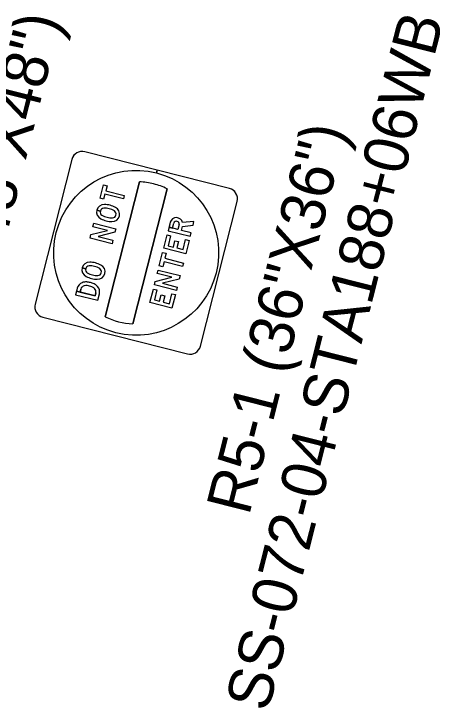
# Model space of a CAD drawing. Extents: x 670257 to 671518, y 737783 to 738188.
# Drawn here: x 670291.975 to 670294.377, y 738129.693 to 738133.598 of the extents above; entities that cross this region are included whole.
import ezdxf

# ---------------------------------------------------------------- set-up
doc = ezdxf.new("R2010")
doc.units = 0
doc.layers.add('Default', color=7, linetype='Continuous')
doc.layers.add('R_SIGN_HWY72', color=7, linetype='Continuous')

msp = doc.modelspace()

# ---------------------------------------------------------------- linework, layer by layer
at = {"layer": 'R_SIGN_HWY72'}
for p, q in [((670293.1871, 738132.6159), (670292.3734, 738132.8223)), ((670293.1871, 738132.6159), (670292.3735, 738132.8222)), ((670292.7803, 738132.7191), (670292.3735, 738132.8222)), ((670292.7803, 738132.7191), (670292.3735, 738132.8222)), ((670292.3006, 738132.7789), (670292.0941, 738131.9649)), ((670292.3006, 738132.7788), (670292.0942, 738131.9649)), ((670292.3006, 738132.7788), (670292.0942, 738131.9649)), ((670292.3006, 738132.7788), (670292.0942, 738131.9649)), ((670292.7803, 738132.7191), (670292.7764, 738132.7036)), ((670293.1871, 738132.6159), (670292.7803, 738132.7191)), ((670293.1871, 738132.6159), (670292.7803, 738132.7191)), ((670292.6812, 738132.6534), (670292.4885, 738131.8939)), ((670292.6435, 738131.8546), (670292.8361, 738132.6141)), ((670293.0241, 738131.7291), (670293.2305, 738132.543)), ((670293.0241, 738131.7291), (670293.2305, 738132.543)), ((670293.0241, 738131.7291), (670293.2305, 738132.543)), ((670293.0241, 738131.7291), (670293.2305, 738132.543)), ((670292.4611, 738132.4887), (670292.4411, 738132.4937)), ((670292.4411, 738132.4937), (670292.4611, 738132.4887)), ((670292.4611, 738132.4887), (670292.4411, 738132.4937)), ((670292.4411, 738132.4937), (670292.4611, 738132.4887)), ((670292.4611, 738132.4887), (670292.4611, 738132.4887)), ((670292.4611, 738132.4887), (670292.4611, 738132.4887)), ((670292.9043, 738132.4133), (670292.8972, 738132.3851)), ((670292.3788, 738132.1642), (670292.3588, 738132.1693)), ((670292.3588, 738132.1693), (670292.3788, 738132.1642)), ((670292.3788, 738132.1642), (670292.3588, 738132.1693)), ((670292.3588, 738132.1693), (670292.3788, 738132.1642)), ((670292.3788, 738132.1642), (670292.3788, 738132.1642)), ((670292.3788, 738132.1642), (670292.3788, 738132.1642)), ((670292.3513, 738132.0499), (670292.347, 738132.0332)), ((670292.4356, 738132.0285), (670292.4313, 738132.0118)), ((670292.4356, 738132.0285), (670292.4313, 738132.0118)), ((670292.4462, 738131.987), (670292.4554, 738132.0235)), ((670292.1375, 738131.8921), (670292.9512, 738131.6857)), ((670292.1375, 738131.8921), (670292.9512, 738131.6857)), ((670292.1375, 738131.892), (670292.9512, 738131.6857)), ((670292.1375, 738131.892), (670292.9512, 738131.6857)), ((670292.1375, 738131.892), (670292.9512, 738131.6857))]:
    msp.add_line(p, q, dxfattribs=at)
for points in [[(670292.7803, 738132.7191), (670292.7764, 738132.7036)], [(670292.7764, 738132.7036), (670292.7803, 738132.7191)], [(670292.7764, 738132.7036), (670292.7803, 738132.7191)], [(670292.4885, 738131.8939), (670292.4885, 738131.8939), (670292.6812, 738132.6534), (670292.6812, 738132.6534)], [(670292.8361, 738132.6141), (670292.8361, 738132.6141), (670292.6435, 738131.8546), (670292.6435, 738131.8546)], [(670292.8544, 738132.4259), (670292.8423, 738132.3782), (670292.9663, 738132.3468), (670292.9712, 738132.3663), (670292.917, 738132.38), (670292.9228, 738132.4028)], [(670292.8544, 738132.4259), (670292.8472, 738132.3978), (670292.8671, 738132.3927), (670292.8742, 738132.4209)], [(670292.8544, 738132.4259), (670292.8472, 738132.3978), (670292.8671, 738132.3927), (670292.8742, 738132.4209)], [(670292.9663, 738132.3468), (670292.9712, 738132.3663), (670292.917, 738132.38), (670292.9228, 738132.4028), (670292.9822, 738132.4095), (670292.9875, 738132.4304), (670292.9235, 738132.424)], [(670292.9663, 738132.3468), (670292.9712, 738132.3663), (670292.917, 738132.38), (670292.9228, 738132.4028), (670292.9822, 738132.4095), (670292.9875, 738132.4304), (670292.9235, 738132.424)], [(670292.9228, 738132.4028), (670292.9822, 738132.4095), (670292.9875, 738132.4304), (670292.9235, 738132.424)], [(670292.9043, 738132.4133), (670292.8972, 738132.3851), (670292.8472, 738132.3977), (670292.8423, 738132.3782), (670292.9663, 738132.3468)], [(670292.9043, 738132.4133), (670292.8972, 738132.3851), (670292.8472, 738132.3977), (670292.8423, 738132.3782), (670292.9663, 738132.3468)], [(670292.8972, 738132.3851), (670292.8671, 738132.3927), (670292.8742, 738132.4209)], [(670292.3314, 738132.0549), (670292.3222, 738132.0185), (670292.4462, 738131.987)], [(670292.4313, 738132.0118), (670292.3272, 738132.0382), (670292.3222, 738132.0185), (670292.4462, 738131.987), (670292.4554, 738132.0235)], [(670292.4313, 738132.0118), (670292.3272, 738132.0382), (670292.3222, 738132.0185), (670292.4462, 738131.987), (670292.4554, 738132.0235)], [(670292.3314, 738132.0549), (670292.3272, 738132.0382), (670292.347, 738132.0332), (670292.3513, 738132.0499)], [(670292.3314, 738132.0549), (670292.3272, 738132.0382), (670292.347, 738132.0332), (670292.3513, 738132.0499)], [(670292.347, 738132.0332), (670292.4313, 738132.0118), (670292.4356, 738132.0285)]]:
    msp.add_lwpolyline(points, dxfattribs=at)
for points in [[(670292.4788, 738132.6361), (670292.4987, 738132.6311), (670292.4915, 738132.603), (670292.5957, 738132.5765), (670292.5907, 738132.557), (670292.4866, 738132.5834), (670292.4795, 738132.5553), (670292.4596, 738132.5603)], [(670292.4788, 738132.6361), (670292.4987, 738132.6311), (670292.4915, 738132.603), (670292.5957, 738132.5765), (670292.5907, 738132.557), (670292.4866, 738132.5834), (670292.4795, 738132.5553), (670292.4596, 738132.5603)], [(670292.4788, 738132.6361), (670292.4987, 738132.6311), (670292.4915, 738132.603), (670292.5957, 738132.5765), (670292.5907, 738132.557), (670292.4866, 738132.5834), (670292.4795, 738132.5553), (670292.4596, 738132.5603)], [(670292.5269, 738132.3053), (670292.4029, 738132.3368), (670292.4079, 738132.3566), (670292.5017, 738132.38), (670292.4192, 738132.4009), (670292.4241, 738132.4205), (670292.5481, 738132.389), (670292.5432, 738132.3695), (670292.4489, 738132.3459), (670292.5319, 738132.3249)], [(670292.5269, 738132.3053), (670292.4029, 738132.3368), (670292.4079, 738132.3566), (670292.5017, 738132.38), (670292.4192, 738132.4009), (670292.4241, 738132.4205), (670292.5481, 738132.389), (670292.5432, 738132.3695), (670292.4489, 738132.3459), (670292.5319, 738132.3249)], [(670292.5269, 738132.3053), (670292.4029, 738132.3368), (670292.4079, 738132.3566), (670292.5017, 738132.38), (670292.4192, 738132.4009), (670292.4241, 738132.4205), (670292.5481, 738132.389), (670292.5432, 738132.3695), (670292.4489, 738132.3459), (670292.5319, 738132.3249)], [(670292.8562, 738132.3499), (670292.842, 738132.2937), (670292.8717, 738132.2862), (670292.8807, 738132.3217), (670292.9006, 738132.3167), (670292.8916, 738132.2812), (670292.9263, 738132.2723), (670292.9405, 738132.3286), (670292.9604, 738132.3235), (670292.9412, 738132.2478), (670292.8172, 738132.2792), (670292.8364, 738132.355)], [(670292.8562, 738132.3499), (670292.842, 738132.2937), (670292.8717, 738132.2862), (670292.8807, 738132.3217), (670292.9006, 738132.3167), (670292.8916, 738132.2812), (670292.9263, 738132.2723), (670292.9405, 738132.3286), (670292.9604, 738132.3235), (670292.9412, 738132.2478), (670292.8172, 738132.2792), (670292.8364, 738132.355)], [(670292.8562, 738132.3499), (670292.842, 738132.2937), (670292.8717, 738132.2862), (670292.8807, 738132.3217), (670292.9006, 738132.3167), (670292.8916, 738132.2812), (670292.9263, 738132.2723), (670292.9405, 738132.3286), (670292.9604, 738132.3235), (670292.9412, 738132.2478), (670292.8172, 738132.2792), (670292.8364, 738132.355)], [(670292.8113, 738132.256), (670292.8311, 738132.251), (670292.824, 738132.2229), (670292.9282, 738132.1965), (670292.9232, 738132.1769), (670292.819, 738132.2033), (670292.8119, 738132.1753), (670292.7921, 738132.1803)], [(670292.8113, 738132.256), (670292.8311, 738132.251), (670292.824, 738132.2229), (670292.9282, 738132.1965), (670292.9232, 738132.1769), (670292.819, 738132.2033), (670292.8119, 738132.1753), (670292.7921, 738132.1803)], [(670292.8113, 738132.256), (670292.8311, 738132.251), (670292.824, 738132.2229), (670292.9282, 738132.1965), (670292.9232, 738132.1769), (670292.819, 738132.2033), (670292.8119, 738132.1753), (670292.7921, 738132.1803)], [(670292.889, 738132.0419), (670292.765, 738132.0734), (670292.77, 738132.0932), (670292.8638, 738132.1166), (670292.7812, 738132.1375), (670292.7862, 738132.1571), (670292.9102, 738132.1256), (670292.9052, 738132.106), (670292.8109, 738132.0825), (670292.8939, 738132.0615)], [(670292.889, 738132.0419), (670292.765, 738132.0734), (670292.77, 738132.0932), (670292.8638, 738132.1166), (670292.7812, 738132.1375), (670292.7862, 738132.1571), (670292.9102, 738132.1256), (670292.9052, 738132.106), (670292.8109, 738132.0825), (670292.8939, 738132.0615)], [(670292.889, 738132.0419), (670292.765, 738132.0734), (670292.77, 738132.0932), (670292.8638, 738132.1166), (670292.7812, 738132.1375), (670292.7862, 738132.1571), (670292.9102, 738132.1256), (670292.9052, 738132.106), (670292.8109, 738132.0825), (670292.8939, 738132.0615)], [(670292.7789, 738132.0451), (670292.7647, 738131.9889), (670292.7944, 738131.9814), (670292.8034, 738132.0169), (670292.8233, 738132.0119), (670292.8143, 738131.9763), (670292.849, 738131.9675), (670292.8632, 738132.0238), (670292.8831, 738132.0187), (670292.8639, 738131.943), (670292.7399, 738131.9744), (670292.7591, 738132.0502)], [(670292.7789, 738132.0451), (670292.7647, 738131.9889), (670292.7944, 738131.9814), (670292.8034, 738132.0169), (670292.8233, 738132.0119), (670292.8143, 738131.9763), (670292.849, 738131.9675), (670292.8632, 738132.0238), (670292.8831, 738132.0187), (670292.8639, 738131.943), (670292.7399, 738131.9744), (670292.7591, 738132.0502)], [(670292.7789, 738132.0451), (670292.7647, 738131.9889), (670292.7944, 738131.9814), (670292.8034, 738132.0169), (670292.8233, 738132.0119), (670292.8143, 738131.9763), (670292.849, 738131.9675), (670292.8632, 738132.0238), (670292.8831, 738132.0187), (670292.8639, 738131.943), (670292.7399, 738131.9744), (670292.7591, 738132.0502)]]:
    msp.add_lwpolyline(points, close=True, dxfattribs=at)
for centre, major_axis, ratio, start_param, end_param in [((670292.3587, 738132.7641), (0.0147, 0.0581), 0.999667, 0, 1.570796), ((670292.3587, 738132.7641), (0.0147, 0.0581), 0.999667, 6.283185, 7.853982), ((670292.3587, 738132.7641), (0.0147, 0.0581), 0.999667, 6.283185, 7.853982), ((670292.3587, 738132.7641), (0.0147, 0.0581), 0.999667, 6.283185, 7.853982), ((670292.6623, 738132.254), (0.114, 0.4496), 0.999667, 0, 6.283158), ((670292.6623, 738132.254), (0.114, 0.4496), 0.999667, 0, 6.283158), ((670292.6623, 738132.254), (0.114, 0.4496), 0.999667, 0, 6.283158), ((670292.6623, 738132.254), (0.0983, 0.3876), 0.999667, 0, 0.201359), ((670292.6623, 738132.254), (0.0983, 0.3876), 0.999667, 6.081826, 6.283153), ((670293.1724, 738132.5578), (0.0147, 0.0581), 0.999667, 4.712389, 6.283185), ((670293.1724, 738132.5577), (0.0147, 0.0581), 0.999667, 4.712388, 6.283186), ((670293.1724, 738132.5577), (0.0147, 0.0581), 0.999667, 4.712388, 6.283186), ((670293.1724, 738132.5577), (0.0147, 0.0581), 0.999667, 4.712388, 6.283186), ((670292.483, 738132.4828), (-0.042, 0.0106), 0.985425, 4.940915, 6.276178), ((670292.483, 738132.4828), (-0.042, 0.0106), 0.985425, 4.940915, 6.27603), ((670292.483, 738132.4828), (-0.042, 0.0106), 0.985425, 4.940915, 6.27603), ((670292.4819, 738132.484), (-0.0207, 0.0053), 0.985425, 5.062003, 6.314032), ((670292.4819, 738132.484), (-0.0207, 0.0053), 0.985425, 5.062003, 6.313732), ((670292.4819, 738132.484), (-0.0207, 0.0053), 0.985425, 5.062003, 6.313732), ((670292.4854, 738132.4102), (-0.0933, 0.0237), 0.985425, 4.688261, 5.016143), ((670292.4854, 738132.4102), (-0.0933, 0.0237), 0.985425, 4.688261, 5.016143), ((670292.4854, 738132.4102), (-0.0933, 0.0237), 0.985425, 4.688261, 5.016143), ((670292.4835, 738132.396), (-0.1272, 0.0323), 0.985425, 4.707364, 4.955713), ((670292.4835, 738132.396), (-0.1272, 0.0323), 0.985425, 4.707364, 4.955713), ((670292.4835, 738132.396), (-0.1272, 0.0323), 0.985425, 4.707364, 4.955713), ((670292.4848, 738132.3957), (-0.1272, 0.0323), 0.985425, 4.469065, 4.717414), ((670292.4848, 738132.3957), (-0.1272, 0.0323), 0.985425, 4.469065, 4.717414), ((670292.4848, 738132.3957), (-0.1272, 0.0323), 0.985425, 4.469065, 4.717414), ((670292.5266, 738132.4717), (-0.042, 0.0106), 0.985425, 3.1486, 4.483863), ((670292.5266, 738132.4717), (-0.042, 0.0106), 0.985425, 3.1486, 4.483863), ((670292.5266, 738132.4717), (-0.042, 0.0106), 0.985425, 3.1486, 4.483863), ((670292.4831, 738132.4834), (-0.042, 0.0106), 0.985425, 0.007008, 1.34227), ((670292.4831, 738132.4834), (-0.042, 0.0106), 0.985425, 0.007008, 1.34227), ((670292.4831, 738132.4834), (-0.042, 0.0106), 0.985425, 0.007008, 1.34227), ((670292.4816, 738132.4828), (-0.0207, 0.0053), 0.985425, 6.252339, 7.504367), ((670292.4816, 738132.4828), (-0.0207, 0.0053), 0.985425, 6.252339, 7.504367), ((670292.4816, 738132.4828), (-0.0207, 0.0053), 0.985425, 6.252339, 7.504367), ((670292.5198, 738132.5461), (-0.0933, 0.0237), 0.985425, 1.267043, 1.594924), ((670292.5198, 738132.5461), (-0.0933, 0.0237), 0.985425, 1.267042, 1.594924), ((670292.5198, 738132.5461), (-0.0933, 0.0237), 0.985425, 1.267042, 1.594924), ((670292.4899, 738132.409), (-0.0933, 0.0237), 0.985425, 4.408635, 4.736517), ((670292.4899, 738132.409), (-0.0933, 0.0237), 0.985425, 4.408635, 4.736517), ((670292.4899, 738132.409), (-0.0933, 0.0237), 0.985425, 4.408635, 4.736517), ((670292.5278, 738132.4711), (-0.0207, 0.0053), 0.985425, 1.920411, 3.172439), ((670292.5278, 738132.4711), (-0.0207, 0.0053), 0.985425, 1.920411, 3.172439), ((670292.5278, 738132.4711), (-0.0207, 0.0053), 0.985425, 1.920411, 3.172439), ((670292.5281, 738132.4723), (-0.0207, 0.0053), 0.985425, 3.110746, 4.362774), ((670292.5281, 738132.4723), (-0.0207, 0.0053), 0.985425, 3.110746, 4.362775), ((670292.5281, 738132.4723), (-0.0207, 0.0053), 0.985425, 3.110746, 4.362775), ((670292.5249, 738132.5594), (-0.1272, 0.0323), 0.985425, 1.327472, 1.575821), ((670292.5249, 738132.5594), (-0.1272, 0.0323), 0.985425, 1.327472, 1.575821), ((670292.5249, 738132.5594), (-0.1272, 0.0323), 0.985425, 1.327472, 1.575821), ((670292.5262, 738132.5591), (-0.1272, 0.0323), 0.985425, 1.565772, 1.814121), ((670292.5262, 738132.5591), (-0.1272, 0.0323), 0.985425, 1.565772, 1.814121), ((670292.5262, 738132.5591), (-0.1272, 0.0323), 0.985425, 1.565772, 1.814121), ((670292.5243, 738132.545), (-0.0933, 0.0237), 0.985425, 1.546668, 1.87455), ((670292.5243, 738132.545), (-0.0933, 0.0237), 0.985425, 1.546668, 1.87455), ((670292.5243, 738132.545), (-0.0933, 0.0237), 0.985425, 1.546668, 1.87455), ((670292.5267, 738132.4723), (-0.042, 0.0106), 0.985425, 1.799323, 3.134585), ((670292.5267, 738132.4723), (-0.042, 0.0106), 0.985425, 1.799323, 3.134585), ((670292.5267, 738132.4723), (-0.042, 0.0106), 0.985425, 1.799323, 3.134585), ((670292.8888, 738132.4165), (-0.0345, 0.0088), 0.985328, 3.608399, 6.264838), ((670292.8888, 738132.4165), (-0.0345, 0.0088), 0.985328, 3.608399, 6.264838), ((670292.8888, 738132.4165), (-0.0345, 0.0088), 0.985328, 3.608399, 6.264838), ((670292.889, 738132.416), (-0.0151, 0.0038), 0.985328, 3.211299, 6.213479), ((670292.889, 738132.416), (-0.0151, 0.0038), 0.985328, 3.211299, 6.213479), ((670292.889, 738132.416), (-0.0151, 0.0038), 0.985328, 3.211299, 6.213479), ((670292.4007, 738132.1584), (-0.042, 0.0106), 0.985425, 4.940915, 6.276178), ((670292.4007, 738132.1584), (-0.042, 0.0106), 0.985425, 4.940915, 6.27603), ((670292.4007, 738132.1584), (-0.042, 0.0106), 0.985425, 4.940915, 6.27603), ((670292.4012, 738132.0716), (-0.1272, 0.0323), 0.985425, 4.707364, 4.955713), ((670292.4012, 738132.0716), (-0.1272, 0.0323), 0.985425, 4.707364, 4.955713), ((670292.4012, 738132.0716), (-0.1272, 0.0323), 0.985425, 4.707364, 4.955713), ((670292.4025, 738132.0713), (-0.1272, 0.0323), 0.985425, 4.469065, 4.717414), ((670292.4025, 738132.0713), (-0.1272, 0.0323), 0.985425, 4.469065, 4.717414), ((670292.4025, 738132.0713), (-0.1272, 0.0323), 0.985425, 4.469065, 4.717414), ((670292.4009, 738132.159), (-0.042, 0.0106), 0.985425, 0.007008, 1.34227), ((670292.4009, 738132.159), (-0.042, 0.0106), 0.985425, 0.007008, 1.34227), ((670292.4009, 738132.159), (-0.042, 0.0106), 0.985425, 0.007008, 1.34227), ((670292.3993, 738132.1584), (-0.0207, 0.0053), 0.985425, 6.252339, 7.504367), ((670292.3993, 738132.1584), (-0.0207, 0.0053), 0.985425, 6.252339, 7.504367), ((670292.3993, 738132.1584), (-0.0207, 0.0053), 0.985425, 6.252339, 7.504367), ((670292.3997, 738132.1596), (-0.0207, 0.0053), 0.985425, 5.062003, 6.314032), ((670292.3997, 738132.1596), (-0.0207, 0.0053), 0.985425, 5.062003, 6.313732), ((670292.3997, 738132.1596), (-0.0207, 0.0053), 0.985425, 5.062003, 6.313732), ((670292.4031, 738132.0858), (-0.0933, 0.0237), 0.985425, 4.688261, 5.016143), ((670292.4031, 738132.0858), (-0.0933, 0.0237), 0.985425, 4.688261, 5.016143), ((670292.4031, 738132.0858), (-0.0933, 0.0237), 0.985425, 4.688261, 5.016143), ((670292.4076, 738132.0846), (-0.0933, 0.0237), 0.985425, 4.408635, 4.736517), ((670292.4076, 738132.0846), (-0.0933, 0.0237), 0.985425, 4.408635, 4.736517), ((670292.4076, 738132.0846), (-0.0933, 0.0237), 0.985425, 4.408635, 4.736517), ((670292.4458, 738132.1479), (-0.0207, 0.0053), 0.985425, 3.110746, 4.362774), ((670292.4458, 738132.1479), (-0.0207, 0.0053), 0.985425, 3.110746, 4.362775), ((670292.4458, 738132.1479), (-0.0207, 0.0053), 0.985425, 3.110746, 4.362775), ((670292.4443, 738132.1473), (-0.042, 0.0106), 0.985425, 3.1486, 4.483863), ((670292.4443, 738132.1473), (-0.042, 0.0106), 0.985425, 3.1486, 4.483863), ((670292.4443, 738132.1473), (-0.042, 0.0106), 0.985425, 3.1486, 4.483863), ((670292.4426, 738132.235), (-0.1272, 0.0323), 0.985425, 1.327472, 1.575821), ((670292.4426, 738132.235), (-0.1272, 0.0323), 0.985425, 1.327472, 1.575821), ((670292.4426, 738132.235), (-0.1272, 0.0323), 0.985425, 1.327472, 1.575821), ((670292.4376, 738132.2217), (-0.0933, 0.0237), 0.985425, 1.267043, 1.594924), ((670292.4376, 738132.2217), (-0.0933, 0.0237), 0.985425, 1.267042, 1.594924), ((670292.4376, 738132.2217), (-0.0933, 0.0237), 0.985425, 1.267042, 1.594924), ((670292.4421, 738132.2205), (-0.0933, 0.0237), 0.985425, 1.546668, 1.87455), ((670292.4421, 738132.2205), (-0.0933, 0.0237), 0.985425, 1.546668, 1.87455), ((670292.4421, 738132.2205), (-0.0933, 0.0237), 0.985425, 1.546668, 1.87455), ((670292.4444, 738132.1479), (-0.042, 0.0106), 0.985425, 1.799323, 3.134585), ((670292.4444, 738132.1479), (-0.042, 0.0106), 0.985425, 1.799323, 3.134585), ((670292.4444, 738132.1479), (-0.042, 0.0106), 0.985425, 1.799323, 3.134585), ((670292.4455, 738132.1467), (-0.0207, 0.0053), 0.985425, 1.920411, 3.172439), ((670292.4455, 738132.1467), (-0.0207, 0.0053), 0.985425, 1.920411, 3.172439), ((670292.4455, 738132.1467), (-0.0207, 0.0053), 0.985425, 1.920411, 3.172439), ((670292.3743, 738132.0447), (-0.0427, 0.0108), 0.994387, 5.308841, 6.296324), ((670292.3743, 738132.0447), (-0.0427, 0.0108), 0.994387, 5.308841, 6.296324), ((670292.3743, 738132.0447), (-0.0427, 0.0108), 0.994387, 5.308841, 6.296324), ((670292.3808, 738132.034), (-0.0546, 0.0139), 0.994387, 4.893794, 5.353227), ((670292.3808, 738132.034), (-0.0546, 0.0139), 0.994387, 4.893794, 5.353227), ((670292.3808, 738132.034), (-0.0546, 0.0139), 0.994387, 4.893794, 5.353227), ((670292.3712, 738131.9476), (-0.1393, 0.0353), 0.994387, 4.719381, 4.866939), ((670292.3712, 738131.9476), (-0.1393, 0.0353), 0.994387, 4.719381, 4.866939), ((670292.3712, 738131.9476), (-0.1393, 0.0353), 0.994387, 4.719381, 4.866939), ((670292.3693, 738131.9481), (-0.1393, 0.0353), 0.994387, 4.557839, 4.705397), ((670292.3693, 738131.9481), (-0.1393, 0.0353), 0.994387, 4.557839, 4.705397), ((670292.3693, 738131.9481), (-0.1393, 0.0353), 0.994387, 4.557839, 4.705397), ((670292.4439, 738132.2347), (-0.1272, 0.0323), 0.985425, 1.565772, 1.814121), ((670292.4439, 738132.2347), (-0.1272, 0.0323), 0.985425, 1.565772, 1.814121), ((670292.4439, 738132.2347), (-0.1272, 0.0323), 0.985425, 1.565772, 1.814121), ((670292.4021, 738132.0287), (-0.0546, 0.0139), 0.994387, 4.071551, 4.530984), ((670292.4021, 738132.0287), (-0.0546, 0.0139), 0.994387, 4.071551, 4.530984), ((670292.4021, 738132.0287), (-0.0546, 0.0139), 0.994387, 4.071551, 4.530984), ((670292.3766, 738132.043), (-0.0254, 0.0064), 0.994387, 5.209958, 6.265172), ((670292.3766, 738132.043), (-0.0254, 0.0064), 0.994387, 5.209958, 6.265172), ((670292.3766, 738132.043), (-0.0254, 0.0064), 0.994387, 5.209958, 6.265172), ((670292.3813, 738132.026), (-0.0426, 0.0108), 0.994387, 4.827156, 5.217241), ((670292.3813, 738132.026), (-0.0426, 0.0108), 0.994387, 4.827156, 5.217241), ((670292.3813, 738132.026), (-0.0426, 0.0108), 0.994387, 4.827156, 5.217241), ((670292.3745, 738131.9741), (-0.0935, 0.0237), 0.994387, 4.688208, 4.829332), ((670292.3745, 738131.9741), (-0.0935, 0.0237), 0.994387, 4.688208, 4.829332), ((670292.3745, 738131.9741), (-0.0935, 0.0237), 0.994387, 4.688208, 4.829332), ((670292.3791, 738131.973), (-0.0935, 0.0237), 0.994387, 4.595446, 4.73657), ((670292.3791, 738131.973), (-0.0935, 0.0237), 0.994387, 4.595446, 4.73657), ((670292.3791, 738131.973), (-0.0935, 0.0237), 0.994387, 4.595446, 4.73657), ((670292.3979, 738132.0218), (-0.0426, 0.0108), 0.994387, 4.207537, 4.597622), ((670292.3979, 738132.0218), (-0.0426, 0.0108), 0.994387, 4.207537, 4.597622), ((670292.3979, 738132.0218), (-0.0426, 0.0108), 0.994387, 4.207537, 4.597622), ((670292.4101, 738132.0345), (-0.0254, 0.0064), 0.994387, 3.159606, 4.21482), ((670292.4101, 738132.0345), (-0.0254, 0.0064), 0.994387, 3.159606, 4.21482), ((670292.4101, 738132.0345), (-0.0254, 0.0064), 0.994387, 3.159606, 4.21482), ((670292.4129, 738132.0349), (-0.0427, 0.0108), 0.994387, 3.128454, 4.115937), ((670292.4129, 738132.0349), (-0.0427, 0.0108), 0.994387, 3.128454, 4.115937), ((670292.4129, 738132.0349), (-0.0427, 0.0108), 0.994387, 3.128454, 4.115937), ((670292.1523, 738131.9502), (0.0147, 0.0581), 0.999667, 1.570796, 3.141593), ((670292.1523, 738131.9502), (0.0147, 0.0581), 0.999667, 1.570796, 3.141593), ((670292.1523, 738131.9502), (0.0147, 0.0581), 0.999667, 1.570796, 3.141593), ((670292.1523, 738131.9502), (0.0147, 0.0581), 0.999667, 1.570796, 3.141593), ((670292.1523, 738131.9502), (0.0147, 0.0581), 0.999667, 1.570796, 3.141593), ((670292.6623, 738132.254), (0.0983, 0.3876), 0.999667, 2.940234, 3.342952), ((670292.6623, 738132.254), (0.0983, 0.3876), 0.999667, 2.940234, 3.342952), ((670292.9659, 738131.7438), (0.0147, 0.0581), 0.999667, 3.141593, 4.712389), ((670292.9659, 738131.7438), (0.0147, 0.0581), 0.999667, 3.141592, 4.71239), ((670292.9659, 738131.7438), (0.0147, 0.0581), 0.999667, 3.141593, 4.712389), ((670292.9659, 738131.7438), (0.0147, 0.0581), 0.999667, 3.141593, 4.712389)]:
    msp.add_ellipse(centre, major_axis=major_axis, ratio=ratio, start_param=start_param, end_param=end_param, dxfattribs=at)

# ---------------------------------------------------------------- texts
at = {"layer": 'Default'}
for s, p in [('SS-072-04-STA188+06WB', (670293.4037, 738129.6665)), ('R1-2 (48"X48"X48")', (670291.5157, 738130.7013)), ('R5-1 (36"X36")', (670293.2969, 738130.771))]:
    msp.add_text(s, height=0.25, rotation=75.7686, dxfattribs=at).set_placement(p)

doc.saveas('drawing.dxf')
